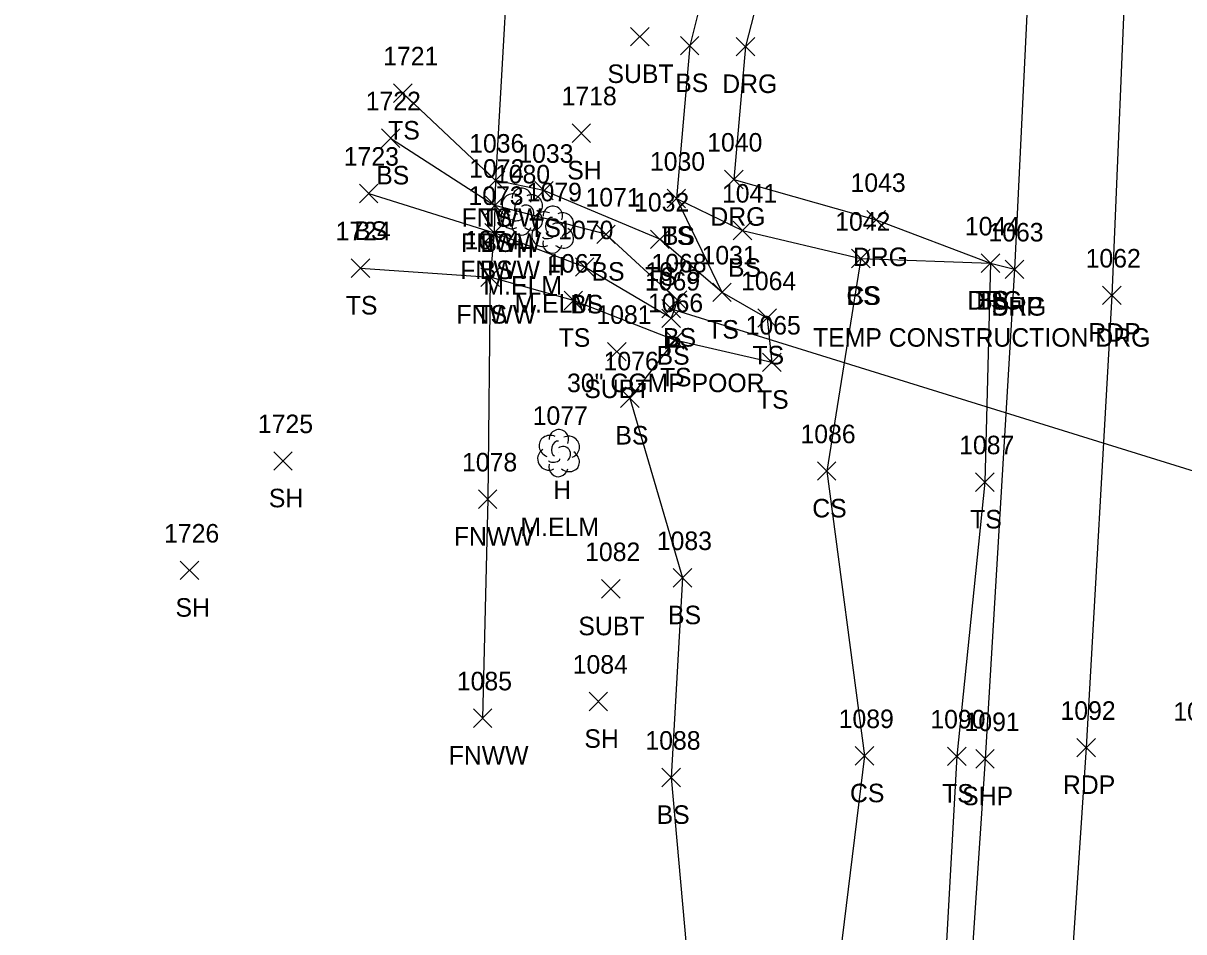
# Model space of a CAD drawing. Extents: x 1443960 to 1446865, y 610387 to 616706.
# Drawn here: x 1446487.6 to 1446612.8, y 611324.5 to 611422.5 of the extents above; entities that cross this region are included whole.
import ezdxf

# ---------------------------------------------------------------- set-up
doc = ezdxf.new("R2010")
doc.units = 0
for name, color, linetype in [('D_A', 7, 'Continuous'), ('D_C', 7, 'Continuous'), ('D_I', 7, 'Continuous'), ('D_TIC', 7, 'Continuous'), ('DCP', 7, 'Continuous'), ('L_A', 7, 'Continuous'), ('L_C', 7, 'Continuous'), ('L_I', 7, 'Continuous'), ('L_TIC', 7, 'Continuous'), ('LELB', 7, 'Continuous'), ('LFNC', 7, 'Continuous'), ('LTD', 7, 'Continuous'), ('P_A', 7, 'Continuous'), ('P_I', 7, 'Continuous'), ('P_TIC', 7, 'Continuous'), ('PET', 7, 'Continuous'), ('PSP', 7, 'Continuous'), ('R_A', 7, 'Continuous'), ('R_C', 7, 'Continuous'), ('R_I', 7, 'Continuous'), ('R_TIC', 7, 'Continuous'), ('RDG', 7, 'Continuous'), ('U_A', 7, 'Continuous'), ('U_I', 7, 'Continuous'), ('U_TIC', 7, 'Continuous')]:
    doc.layers.add(name, color=color, linetype=linetype)

msp = doc.modelspace()

# ---------------------------------------------------------------- linework, layer by layer
at = {"layer": 'D_TIC'}
for points in [[(1446556.44, 611390.72), (1446558.44, 611392.72)], [(1446558.44, 611390.72), (1446556.44, 611392.72)]]:
    msp.add_lwpolyline(points, dxfattribs=at)
at = {"layer": 'DCP'}
msp.add_lwpolyline([(1446557.44, 611391.72), (1446674.45, 611355.4)], dxfattribs=at)
at = {"layer": 'L_TIC'}
for points in [[(1446558.45, 611419.08), (1446560.45, 611421.08)], [(1446560.45, 611419.08), (1446558.45, 611421.08)], [(1446527.51, 611413.96), (1446529.51, 611415.96)], [(1446529.51, 611413.96), (1446527.51, 611415.96)], [(1446526.19, 611409.12), (1446528.19, 611411.12)], [(1446528.19, 611409.12), (1446526.19, 611411.12)], [(1446546.76, 611409.66), (1446548.76, 611411.66)], [(1446548.76, 611409.66), (1446546.76, 611411.66)], [(1446537.49, 611404.55), (1446539.49, 611406.55)], [(1446539.49, 611404.55), (1446537.49, 611406.55)], [(1446537.49, 611404.55), (1446539.49, 611406.55)], [(1446539.49, 611404.55), (1446537.49, 611406.55)], [(1446523.82, 611403.14), (1446525.82, 611405.14)], [(1446525.82, 611403.14), (1446523.82, 611405.14)], [(1446542.73, 611403.45), (1446544.73, 611405.45)], [(1446544.73, 611403.45), (1446542.73, 611405.45)], [(1446557.01, 611402.6), (1446559.01, 611404.6)], [(1446559.01, 611402.6), (1446557.01, 611404.6)], [(1446557.01, 611402.6), (1446559.01, 611404.6)], [(1446559.01, 611402.6), (1446557.01, 611404.6)], [(1446537.43, 611401.84), (1446539.43, 611403.84)], [(1446539.43, 611401.84), (1446537.43, 611403.84)], [(1446537.43, 611401.84), (1446539.43, 611403.84)], [(1446539.43, 611401.84), (1446537.43, 611403.84)], [(1446537.35, 611398.91), (1446539.35, 611400.91)], [(1446539.35, 611398.91), (1446537.35, 611400.91)], [(1446537.35, 611398.91), (1446539.35, 611400.91)], [(1446539.35, 611398.91), (1446537.35, 611400.91)], [(1446564.14, 611399.16), (1446566.14, 611401.16)], [(1446566.14, 611399.16), (1446564.14, 611401.16)], [(1446549.42, 611398.74), (1446551.42, 611400.74)], [(1446551.42, 611398.74), (1446549.42, 611400.74)], [(1446555.22, 611398.2), (1446557.22, 611400.2)], [(1446557.22, 611398.2), (1446555.22, 611400.2)], [(1446522.94, 611395.09), (1446524.94, 611397.09)], [(1446524.94, 611395.09), (1446522.94, 611397.09)], [(1446547.12, 611395.21), (1446549.12, 611397.21)], [(1446549.12, 611395.21), (1446547.12, 611397.21)], [(1446576.92, 611396.13), (1446578.92, 611398.13)], [(1446578.92, 611396.13), (1446576.92, 611398.13)], [(1446576.92, 611396.13), (1446578.92, 611398.13)], [(1446578.92, 611396.13), (1446576.92, 611398.13)], [(1446590.91, 611395.62), (1446592.91, 611397.62)], [(1446592.91, 611395.62), (1446590.91, 611397.62)], [(1446590.91, 611395.62), (1446592.91, 611397.62)], [(1446592.91, 611395.62), (1446590.91, 611397.62)], [(1446536.93, 611394.11), (1446538.93, 611396.11)], [(1446538.93, 611394.11), (1446536.93, 611396.11)], [(1446536.93, 611394.11), (1446538.93, 611396.11)], [(1446538.93, 611394.11), (1446536.93, 611396.11)], [(1446545.9, 611391.61), (1446547.9, 611393.61)], [(1446547.9, 611391.61), (1446545.9, 611393.61)], [(1446557.13, 611391.63), (1446559.13, 611393.63)], [(1446559.13, 611391.63), (1446557.13, 611393.63)], [(1446557.13, 611391.63), (1446559.13, 611393.63)], [(1446559.13, 611391.63), (1446557.13, 611393.63)], [(1446561.93, 611392.49), (1446563.93, 611394.49)], [(1446563.93, 611392.49), (1446561.93, 611394.49)], [(1446561.93, 611392.49), (1446563.93, 611394.49)], [(1446563.93, 611392.49), (1446561.93, 611394.49)], [(1446556.44, 611389.68), (1446558.44, 611391.68)], [(1446558.44, 611389.68), (1446556.44, 611391.68)], [(1446566.81, 611389.71), (1446568.81, 611391.71)], [(1446568.81, 611389.71), (1446566.81, 611391.71)], [(1446556.83, 611387.34), (1446558.83, 611389.34)], [(1446558.83, 611387.34), (1446556.83, 611389.34)], [(1446567.3, 611384.93), (1446569.3, 611386.93)], [(1446569.3, 611384.93), (1446567.3, 611386.93)], [(1446551.99, 611381.07), (1446553.99, 611383.07)], [(1446553.99, 611381.07), (1446551.99, 611383.07)], [(1446514.57, 611374.3), (1446516.57, 611376.3)], [(1446516.57, 611374.3), (1446514.57, 611376.3)], [(1446573.23, 611373.21), (1446575.23, 611375.21)], [(1446575.23, 611373.21), (1446573.23, 611375.21)], [(1446590.29, 611372.02), (1446592.29, 611374.02)], [(1446592.29, 611372.02), (1446590.29, 611374.02)], [(1446536.66, 611370.17), (1446538.66, 611372.17)], [(1446538.66, 611370.17), (1446536.66, 611372.17)], [(1446504.49, 611362.5), (1446506.49, 611364.5)], [(1446506.49, 611362.5), (1446504.49, 611364.5)], [(1446557.67, 611361.69), (1446559.67, 611363.69)], [(1446559.67, 611361.69), (1446557.67, 611363.69)], [(1446548.6, 611348.36), (1446550.6, 611350.36)], [(1446550.6, 611348.36), (1446548.6, 611350.36)], [(1446536.11, 611346.56), (1446538.11, 611348.56)], [(1446538.11, 611346.56), (1446536.11, 611348.56)], [(1446577.3, 611342.49), (1446579.3, 611344.49)], [(1446579.3, 611342.49), (1446577.3, 611344.49)], [(1446587.27, 611342.45), (1446589.27, 611344.45)], [(1446589.27, 611342.45), (1446587.27, 611344.45)], [(1446556.44, 611340.16), (1446558.44, 611342.16)], [(1446558.44, 611340.16), (1446556.44, 611342.16)]]:
    msp.add_lwpolyline(points, dxfattribs=at)
at = {"layer": 'LELB'}
for points in [[(1446592.97, 611434.29), (1446582.27, 611436.43), (1446568.84, 611436.61), (1446562.29, 611431.48), (1446559.45, 611420.08), (1446558.01, 611403.6), (1446565.14, 611400.16), (1446577.92, 611397.13), (1446591.91, 611396.62)], [(1446528.51, 611414.96), (1446538.49, 611405.55)], [(1446527.19, 611410.12), (1446538.43, 611402.84)], [(1446562.93, 611393.49), (1446556.22, 611399.2), (1446543.73, 611404.45), (1446538.49, 611405.55)], [(1446524.82, 611404.14), (1446538.35, 611399.91)], [(1446558.01, 611403.6), (1446562.93, 611393.49), (1446567.81, 611390.71), (1446568.3, 611385.93), (1446557.83, 611388.34), (1446546.9, 611392.61), (1446537.93, 611395.11)], [(1446558.13, 611392.63), (1446550.42, 611399.74), (1446538.43, 611402.84)], [(1446558.13, 611392.63), (1446557.44, 611390.68), (1446548.12, 611396.21), (1446538.35, 611399.91)], [(1446577.92, 611397.13), (1446574.23, 611374.21), (1446578.3, 611343.49), (1446573.49, 611304.16), (1446568.84, 611262.33), (1446567.89, 611213.77), (1446568.92, 611197.56), (1446566.72, 611186.09)], [(1446523.94, 611396.09), (1446537.93, 611395.11)], [(1446591.91, 611396.62), (1446591.29, 611373.02), (1446588.27, 611343.45), (1446585.99, 611302.83), (1446583.49, 611260.98), (1446579.14, 611211.88), (1446577.5, 611193.46), (1446576.67, 611181), (1446577.51, 611168.64)], [(1446557.83, 611388.34), (1446552.99, 611382.07)], [(1446552.99, 611382.07), (1446558.67, 611362.69), (1446557.44, 611341.16), (1446560.67, 611304.99), (1446555.64, 611264.16), (1446556.53, 611215.55), (1446554.81, 611203.13), (1446541.6, 611207.37), (1446517.97, 611221.87), (1446506.75, 611230.08), (1446482.61, 611245.67), (1446443.05, 611268.8), (1446411.93, 611283.54), (1446399.45, 611289.73)]]:
    msp.add_lwpolyline(points, dxfattribs=at)
at = {"layer": 'LFNC'}
msp.add_lwpolyline([(1446541.83, 611473.4), (1446540.48, 611440.24), (1446538.49, 611405.55), (1446538.43, 611402.84), (1446538.35, 611399.91), (1446537.93, 611395.11), (1446537.66, 611371.17), (1446537.11, 611347.56)], dxfattribs=at)
at = {"layer": 'LTD'}
for p, q in [((1446541.3, 611402.23), (1446541.3, 611402.23)), ((1446541.3, 611402.23), (1446541.3, 611402.23)), ((1446544.65, 611400.3), (1446544.65, 611400.3)), ((1446544.65, 611400.3), (1446544.65, 611400.3)), ((1446545.28, 611376.19), (1446545.28, 611376.19)), ((1446545.28, 611376.19), (1446545.28, 611376.19))]:
    msp.add_line(p, q, dxfattribs=at)
for centre in [(1446541.35, 611403.66), (1446544.69, 611401.73), (1446545.33, 611377.63)]:
    msp.add_arc(centre, 1.05, 335.5272, 180.9563, dxfattribs=at)
for centre, major_axis, ratio, start_param, end_param in [((1446540.51, 611402.9), (1.21, -0.51), 0.895232, 1.570796, 4.712389), ((1446541.09, 611402.69), (-0.208, -0.792), 0.645439, 3.141593, 6.283185), ((1446542.34, 611402.81), (-1.14, -0.48), 0.949671, 1.570796, 4.712389), ((1446540.22, 611401.52), (0.58, -1.04), 0.959034, 3.141593, 6.283185), ((1446541.8, 611402.06), (-0.5, 0.667), 0.989748, 3.141593, 6.283185), ((1446542.3, 611401.4), (-1.09, 0.79), 0.841452, 1.570796, 4.712389), ((1446543.86, 611400.96), (1.21, -0.51), 0.895232, 1.570796, 4.712389), ((1446545.69, 611400.88), (-1.14, -0.48), 0.949671, 1.570796, 4.712389), ((1446541.3, 611400.73), (0.26, 1.06), 0.942809, 1.570796, 4.712389), ((1446540.84, 611401.48), (-0.625, -0.083), 0.423636, 0, 3.141593), ((1446544.44, 611400.76), (-0.208, -0.792), 0.645439, 3.141593, 6.283185), ((1446545.15, 611400.13), (-0.5, 0.667), 0.989748, 3.141593, 6.283185), ((1446543.56, 611399.59), (0.58, -1.04), 0.959034, 3.141593, 6.283185), ((1446544.19, 611399.55), (-0.625, -0.083), 0.423636, 0, 3.141593), ((1446545.65, 611399.46), (-1.09, 0.79), 0.841452, 1.570796, 4.712389), ((1446544.65, 611398.8), (0.26, 1.06), 0.942809, 1.570796, 4.712389), ((1446544.49, 611376.86), (1.21, -0.51), 0.895232, 1.570796, 4.712389), ((1446545.08, 611376.65), (-0.208, -0.792), 0.645439, 3.141593, 6.283185), ((1446546.33, 611376.78), (-1.14, -0.48), 0.949671, 1.570796, 4.712389), ((1446544.2, 611375.49), (0.58, -1.04), 0.959034, 3.141593, 6.283185), ((1446545.78, 611376.03), (-0.5, 0.667), 0.989748, 3.141593, 6.283185), ((1446546.28, 611375.36), (-1.09, 0.79), 0.841452, 1.570796, 4.712389), ((1446545.29, 611374.69), (0.26, 1.06), 0.942809, 1.570796, 4.712389), ((1446544.83, 611375.44), (-0.625, -0.083), 0.423636, 0, 3.141593)]:
    msp.add_ellipse(centre, major_axis=major_axis, ratio=ratio, start_param=start_param, end_param=end_param, dxfattribs=at)
at = {"layer": 'P_TIC'}
for points in [[(1446593.49, 611394.97), (1446595.49, 611396.97)], [(1446595.49, 611394.97), (1446593.49, 611396.97)], [(1446603.98, 611392.16), (1446605.98, 611394.16)], [(1446605.98, 611392.16), (1446603.98, 611394.16)], [(1446601.22, 611343.38), (1446603.22, 611345.38)], [(1446603.22, 611343.38), (1446601.22, 611345.38)], [(1446590.31, 611342.17), (1446592.31, 611344.17)], [(1446592.31, 611342.17), (1446590.31, 611344.17)], [(1446590.31, 611342.17), (1446592.31, 611344.17)], [(1446592.31, 611342.17), (1446590.31, 611344.17)]]:
    msp.add_lwpolyline(points, dxfattribs=at)
at = {"layer": 'PET'}
msp.add_lwpolyline([(1446607.25, 611453.94), (1446606.67, 611433.53), (1446604.98, 611393.16), (1446602.22, 611344.38), (1446599.36, 611301.15), (1446596.11, 611259.06), (1446592.2, 611211.24), (1446588.27, 611166.36), (1446587.47, 611154.32)], dxfattribs=at)
at = {"layer": 'PSP'}
for points in [[(1446596.93, 611454.28), (1446596.27, 611433.14), (1446594.49, 611395.97), (1446591.31, 611343.17)], [(1446591.31, 611343.17), (1446588.59, 611302.46), (1446585.58, 611261), (1446582.23, 611211.77), (1446577.51, 611168.64), (1446576.96, 611160.22), (1446577.27, 611159.61)]]:
    msp.add_lwpolyline(points, dxfattribs=at)
at = {"layer": 'R_TIC'}
for points in [[(1446564.47, 611418.98), (1446566.47, 611420.98)], [(1446566.47, 611418.98), (1446564.47, 611420.98)], [(1446563.2, 611404.66), (1446565.2, 611406.66)], [(1446565.2, 611404.66), (1446563.2, 611406.66)], [(1446578.57, 611400.31), (1446580.57, 611402.31)], [(1446580.57, 611400.31), (1446578.57, 611402.31)], [(1446590.91, 611395.62), (1446592.91, 611397.62)], [(1446592.91, 611395.62), (1446590.91, 611397.62)], [(1446593.49, 611394.97), (1446595.49, 611396.97)], [(1446595.49, 611394.97), (1446593.49, 611396.97)]]:
    msp.add_lwpolyline(points, dxfattribs=at)
at = {"layer": 'RDG'}
msp.add_lwpolyline([(1446596.27, 611433.14), (1446592.97, 611434.29), (1446582.25, 611433.06), (1446571.29, 611431.63), (1446567.65, 611428.55), (1446565.47, 611419.98), (1446564.2, 611405.66), (1446579.57, 611401.31), (1446591.91, 611396.62), (1446594.49, 611395.97)], dxfattribs=at)
at = {"layer": 'U_TIC'}
for points in [[(1446553.08, 611420.06), (1446555.08, 611422.06)], [(1446555.08, 611420.06), (1446553.08, 611422.06)], [(1446550.58, 611386.08), (1446552.58, 611388.08)], [(1446552.58, 611386.08), (1446550.58, 611388.08)], [(1446549.95, 611360.5), (1446551.95, 611362.5)], [(1446551.95, 611360.5), (1446549.95, 611362.5)]]:
    msp.add_lwpolyline(points, dxfattribs=at)

# ---------------------------------------------------------------- texts
at = {"layer": 'D_A'}
msp.add_text('P', height=2, dxfattribs=at).set_placement((1446556.82, 611386.72))
at = {"layer": 'D_C'}
msp.add_text('30" CGMP POOR', height=2, dxfattribs=at).set_placement((1446546.22, 611382.72))
at = {"layer": 'D_I'}
msp.add_text('1075', height=2, dxfattribs=at).set_placement((1446554.67, 611394.72))
at = {"layer": 'L_A'}
for s, p in [('BS', (1446557.89, 611415.08)), ('TS', (1446526.92, 611409.96)), ('BS', (1446525.63, 611405.12)), ('SH', (1446546.24, 611405.66)), ('FNWW', (1446534.84, 611400.55)), ('TS', (1446536.9, 611400.55)), ('BS', (1446523.26, 611399.14)), ('TS', (1446542.14, 611399.45)), ('FNWW', (1446534.78, 611397.84)), ('BS', (1446536.87, 611397.84)), ('TS', (1446556.42, 611398.6)), ('BS', (1446556.45, 611398.6)), ('H', (1446540.73, 611397.23)), ('H', (1446544.08, 611395.3)), ('BS', (1446563.58, 611395.16)), ('FNWW', (1446534.69, 611394.91)), ('BS', (1446536.79, 611394.91)), ('BS', (1446548.86, 611394.74)), ('TS', (1446554.63, 611394.2)), ('CS', (1446576.36, 611392.13)), ('BS', (1446576.36, 611392.13)), ('TS', (1446590.32, 611391.62)), ('BS', (1446590.35, 611391.62)), ('TS', (1446522.35, 611391.09)), ('FNWW', (1446534.28, 611390.11)), ('TS', (1446536.34, 611390.11)), ('BS', (1446546.56, 611391.21)), ('TS', (1446545.31, 611387.61)), ('BS', (1446556.57, 611387.63)), ('BS', (1446556.57, 611387.63)), ('TS', (1446561.34, 611388.49)), ('TS', (1446561.34, 611388.49)), ('BS', (1446555.88, 611385.68)), ('TS', (1446566.22, 611385.71)), ('TS', (1446556.24, 611383.34)), ('TS', (1446566.71, 611380.93)), ('BS', (1446551.43, 611377.07)), ('SH', (1446514.05, 611370.3)), ('H', (1446544.72, 611371.19)), ('CS', (1446572.67, 611369.21)), ('TS', (1446589.7, 611368.02)), ('FNWW', (1446534.01, 611366.17)), ('SH', (1446503.98, 611358.5)), ('BS', (1446557.11, 611357.69)), ('SH', (1446548.09, 611344.36)), ('FNWW', (1446533.45, 611342.56)), ('CS', (1446576.74, 611338.49)), ('TS', (1446586.68, 611338.45)), ('BS', (1446555.88, 611336.16))]:
    msp.add_text(s, height=2, dxfattribs=at).set_placement(p)
at = {"layer": 'L_C'}
for p in [(1446537.2, 611393.23), (1446540.55, 611391.3), (1446541.19, 611367.19)]:
    msp.add_text('M.ELM', height=2, dxfattribs=at).set_placement(p)
at = {"layer": 'L_I'}
for s, p in [('1721', (1446526.38, 611417.96)), ('1722', (1446524.5, 611413.12)), ('1718', (1446545.63, 611413.66)), ('1036', (1446535.66, 611408.55)), ('1036', (1446535.66, 611408.55)), ('1723', (1446522.13, 611407.14)), ('1033', (1446540.96, 611407.45)), ('1030', (1446555.16, 611406.6)), ('1030', (1446555.16, 611406.6)), ('1072', (1446535.66, 611405.84)), ('1072', (1446535.66, 611405.84)), ('1080', (1446538.44, 611405.23)), ('1073', (1446535.58, 611402.91)), ('1073', (1446535.58, 611402.91)), ('1079', (1446541.87, 611403.3)), ('1071', (1446548.21, 611402.74)), ('1041', (1446562.93, 611403.16)), ('1032', (1446553.45, 611402.2)), ('1042', (1446575.15, 611400.13)), ('1042', (1446575.15, 611400.13)), ('1724', (1446521.25, 611399.09)), ('1070', (1446545.27, 611399.21)), ('1044', (1446589.14, 611399.62)), ('1044', (1446589.14, 611399.62)), ('1074', (1446535.16, 611398.11)), ('1074', (1446535.16, 611398.11)), ('1031', (1446560.73, 611396.49)), ('1031', (1446560.73, 611396.49)), ('1067', (1446544.08, 611395.61)), ('1068', (1446555.32, 611395.63)), ('1068', (1446555.32, 611395.63)), ('1069', (1446554.62, 611393.68)), ('1064', (1446564.99, 611393.71)), ('1066', (1446554.95, 611391.34)), ('1065', (1446565.48, 611388.93)), ('1076', (1446550.16, 611385.07)), ('1077', (1446542.51, 611379.19)), ('1725', (1446512.87, 611378.3)), ('1086', (1446571.4, 611377.21)), ('1087', (1446588.52, 611376.02)), ('1078', (1446534.89, 611374.17)), ('1726', (1446502.75, 611366.5)), ('1083', (1446555.9, 611365.69)), ('1084', (1446546.83, 611352.36)), ('1085', (1446534.33, 611350.56)), ('1089', (1446575.52, 611346.49)), ('1090', (1446585.41, 611346.45)), ('1088', (1446554.67, 611344.16))]:
    msp.add_text(s, height=2, dxfattribs=at).set_placement(p)
at = {"layer": 'P_A'}
for s, p in [('SHP', (1446592.03, 611390.97)), ('RDP', (1446602.46, 611388.16)), ('RDP', (1446599.71, 611339.38)), ('SHP', (1446588.84, 611338.17)), ('SHP', (1446588.84, 611338.17))]:
    msp.add_text(s, height=2, dxfattribs=at).set_placement(p)
at = {"layer": 'P_I'}
for s, p in [('1063', (1446591.67, 611398.97)), ('1062', (1446602.16, 611396.16)), ('1091', (1446589.1, 611346.17)), ('1091', (1446589.1, 611346.17)), ('1092', (1446599.45, 611347.38)), ('1093', (1446611.62, 611347.28))]:
    msp.add_text(s, height=2, dxfattribs=at).set_placement(p)
at = {"layer": 'R_A'}
for p in [(1446562.96, 611414.98), (1446561.68, 611400.66), (1446577.05, 611396.31), (1446589.39, 611391.62), (1446591.98, 611390.97)]:
    msp.add_text('DRG', height=2, dxfattribs=at).set_placement(p)
at = {"layer": 'R_C'}
msp.add_text('TEMP CONSTRUCTION DRG', height=2, dxfattribs=at).set_placement((1446572.75, 611387.62))
at = {"layer": 'R_I'}
for s, p in [('1040', (1446561.34, 611408.66)), ('1043', (1446576.8, 611404.31)), ('1044', (1446589.14, 611399.62)), ('1063', (1446591.67, 611398.97))]:
    msp.add_text(s, height=2, dxfattribs=at).set_placement(p)
at = {"layer": 'U_A'}
for p in [(1446550.58, 611416.06), (1446548.08, 611382.08), (1446547.44, 611356.5)]:
    msp.add_text('SUBT', height=2, dxfattribs=at).set_placement(p)
at = {"layer": 'U_I'}
for s, p in [('1081', (1446549.38, 611390.08)), ('1082', (1446548.17, 611364.5))]:
    msp.add_text(s, height=2, dxfattribs=at).set_placement(p)

doc.saveas('drawing.dxf')
